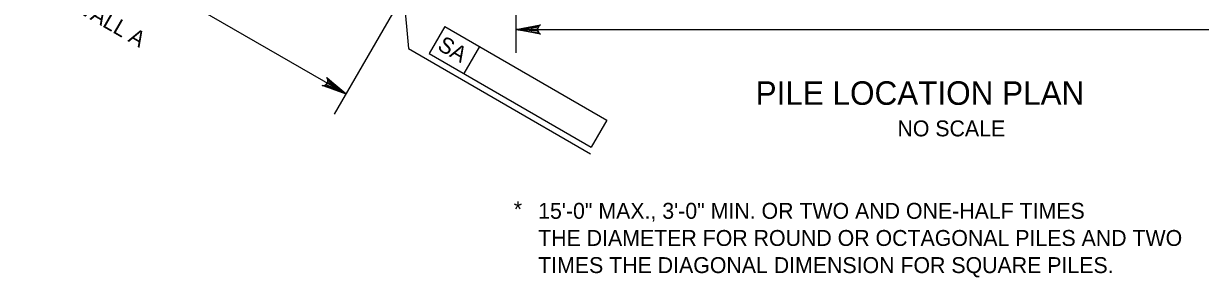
# Model space of a CAD drawing. Extents: x 638340 to 640242, y 295465 to 298435.
# Drawn here: x 639417.6 to 639639.2, y 296418.4 to 296466.2 of the extents above; entities that cross this region are included whole.
import ezdxf

# ---------------------------------------------------------------- set-up
doc = ezdxf.new("R2010")
doc.units = 0
for name, color, linetype in [('2', 7, 'Continuous'), ('4', 7, 'Continuous'), ('Level 2', 7, 'Continuous')]:
    doc.layers.add(name, color=color, linetype=linetype)

msp = doc.modelspace()

# ---------------------------------------------------------------- linework, layer by layer
at = {"layer": 'Level 2'}
for p, q in [((639510.35, 296506.88), (639510.35, 296460.68)), ((639478.34, 296452.97), (639402.52, 296496.75)), ((639488.32, 296481.34), (639490.13, 296461.52)), ((639487.78, 296469.31), (639476.13, 296449.14)), ((639496.94, 296465.66), (639493.99, 296460.56)), ((639496.94, 296465.66), (639527.44, 296448.03)), ((639510.35, 296465.1), (639669.75, 296465.1)), ((639490.13, 296461.52), (639524.42, 296441.72)), ((639503.47, 296461.89), (639500.53, 296456.79)), ((639493.99, 296460.56), (639524.5, 296442.93)), ((639527.44, 296448.03), (639524.5, 296442.93))]:
    msp.add_line(p, q, dxfattribs=at)
for points in [[(639510.35, 296465.1), (639515.01, 296465.97), (639514.65, 296465.73), (639514.46, 296465.41), (639514.41, 296465.1), (639514.46, 296464.79), (639514.65, 296464.48), (639515.01, 296464.23), (639510.35, 296465.1), (639514.65, 296464.48), (639514.46, 296464.79), (639510.35, 296465.1), (639514.41, 296465.1), (639514.46, 296465.41), (639510.35, 296465.1), (639514.65, 296465.73)], [(639478.34, 296452.97), (639473.88, 296454.54), (639474.32, 296454.58), (639474.63, 296454.75), (639474.83, 296455), (639474.94, 296455.29), (639474.94, 296455.65), (639474.75, 296456.05), (639478.34, 296452.97), (639474.94, 296455.65), (639474.94, 296455.29), (639478.34, 296452.97), (639474.83, 296455), (639474.63, 296454.75), (639478.34, 296452.97), (639474.32, 296454.58)]]:
    msp.add_lwpolyline(points, dxfattribs=at)
for points in [[(639513.3, 296465.59), (639513.3, 296464.61), (639510.35, 296465.1)], [(639476.04, 296454.87), (639475.55, 296454.02), (639478.34, 296452.97)]]:
    msp.add_lwpolyline(points, close=True, dxfattribs=at)

# ---------------------------------------------------------------- texts
at = {"layer": '2'}
msp.add_text('NO SCALE', height=3, dxfattribs=at).set_placement((639582.18, 296444.98))
at = {"layer": '4'}
msp.add_text('PILE LOCATION PLAN', height=4.4294, dxfattribs=at).set_placement((639555.48, 296450.92))
at = {"layer": 'Level 2'}
for s, rotation, p in [('WINGWALL A', 330, (639417.28, 296474.44)), ('SA', 329.9382, (639495.37, 296461.44)), ('*', 359.9382, (639509.94, 296429.77))]:
    msp.add_text(s, height=3, rotation=rotation, dxfattribs=at).set_placement(p)
for s, p in [('15\'-0" MAX., 3\'-0" MIN. OR TWO AND ONE-HALF TIMES', (639514.54, 296429.46)), ('THE DIAMETER FOR ROUND OR OCTAGONAL PILES AND TWO', (639514.54, 296424.35)), ('TIMES THE DIAGONAL DIMENSION FOR SQUARE PILES.', (639514.54, 296419.24))]:
    msp.add_text(s, height=3.0001, dxfattribs=at).set_placement(p)

doc.saveas('drawing.dxf')
